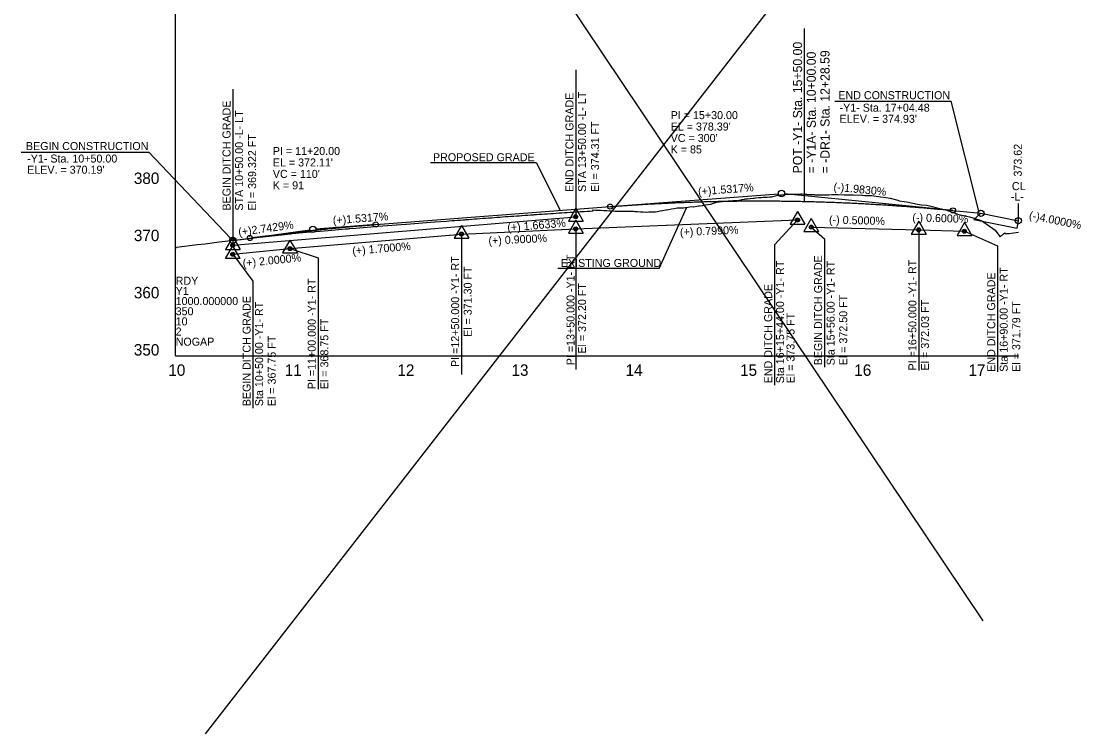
# Model space of a CAD drawing. Extents: x 1625686 to 1640492, y 1161393 to 1175642.
# Drawn here: x 1635777 to 1636704, y 1173205 to 1173828 of the extents above; entities that cross this region are included whole.
import ezdxf

# ---------------------------------------------------------------- set-up
doc = ezdxf.new("R2010")
doc.units = 0
for name, color, linetype in [('Exist Profile Cell', 7, 'Continuous'), ('Exist Vertical Profile Ground Line', 7, 'Continuous'), ('Exist Vertical Profile Horizontal Axis Label Major', 7, 'Continuous'), ('Exist Vertical Profile Vertical Axis Label', 7, 'Continuous'), ('Prop PFL Text', 7, 'Continuous'), ('Prop Vertical Profile Curve Label', 7, 'Continuous'), ('Prop Vertical Profile Ditch Grade Left', 7, 'Continuous'), ('Prop Vertical Profile Ditch Grade Left Label', 7, 'Continuous'), ('Prop Vertical Profile Ditch Grade Right', 7, 'Continuous'), ('Prop Vertical Profile Ditch Grade Right Label', 7, 'Continuous'), ('Prop Vertical Profile Grade', 7, 'Continuous'), ('Prop Vertical Profile Grade Label', 7, 'Continuous'), ('Prop VPI Ditch Grade Left Label', 7, 'Continuous'), ('Prop VPI Ditch Grade Right Label', 7, 'Continuous'), ('Prop VPI Label', 7, 'Continuous'), ('Scratch_Level_3', 7, 'Continuous')]:
    doc.layers.add(name, color=color, linetype=linetype)

msp = doc.modelspace()

# ---------------------------------------------------------------- linework, layer by layer
at = {"layer": 'Exist Profile Cell'}
for q in [(1635911.78, 1174035.94), (1636649.02, 1173535.94), (1635911.78, 1173535.94)]:
    msp.add_line((1635911.78, 1173535.94), q, dxfattribs=at)
at = {"layer": 'Exist Vertical Profile Ground Line'}
msp.add_lwpolyline([(1635911.78, 1173629.69), (1635912.5, 1173630.93), (1635930.84, 1173633.15), (1635937.5, 1173633.96), (1635949.9, 1173635.46), (1635962.76, 1173637.02), (1635968.96, 1173637.73), (1635987.54, 1173639.86), (1635988.02, 1173639.92), (1636007.08, 1173642.1), (1636012.54, 1173642.73), (1636013.03, 1173642.78), (1636013.62, 1173642.83), (1636026.15, 1173643.91), (1636038.32, 1173644.96), (1636045.21, 1173645.56), (1636060.28, 1173646.86), (1636063.04, 1173647.1), (1636063.8, 1173647.16), (1636069.51, 1173647.62), (1636088.9, 1173649.18), (1636113.26, 1173651.14), (1636113.61, 1173651.16), (1636138.26, 1173653), (1636138.61, 1173653.02), (1636148.59, 1173653.76), (1636151.05, 1173653.94), (1636153.51, 1173654.12), (1636155.97, 1173654.3), (1636158.43, 1173654.48), (1636160.89, 1173654.65), (1636163.35, 1173654.82), (1636165.18, 1173654.95), (1636166.05, 1173655.02), (1636168.28, 1173655.2), (1636170.74, 1173655.4), (1636173.2, 1173655.59), (1636175.66, 1173655.78), (1636178.12, 1173655.97), (1636180.58, 1173656.16), (1636183.04, 1173656.34), (1636185.5, 1173656.53), (1636187.96, 1173656.71), (1636190.43, 1173656.89), (1636192.89, 1173657.08), (1636194.17, 1173657.18), (1636195.35, 1173657.26), (1636197.81, 1173657.44), (1636200.27, 1173657.61), (1636202.73, 1173657.78), (1636205.19, 1173657.95), (1636207.65, 1173658.12), (1636210.11, 1173658.29), (1636212.58, 1173658.45), (1636214.37, 1173658.57), (1636215.04, 1173658.62), (1636217.5, 1173658.8), (1636219.96, 1173658.98), (1636222.42, 1173659.16), (1636224.88, 1173659.34), (1636225.29, 1173659.37), (1636227.34, 1173659.51), (1636229.8, 1173659.68), (1636232.26, 1173659.84), (1636234.73, 1173660), (1636237.19, 1173660.17), (1636239.65, 1173660.33), (1636242.11, 1173660.49), (1636244.57, 1173660.66), (1636247.03, 1173660.82), (1636249.49, 1173660.98), (1636251.95, 1173661.14), (1636254.41, 1173661.3), (1636256.87, 1173661.46), (1636259.34, 1173661.61), (1636261.8, 1173661.76), (1636263.1, 1173661.84), (1636264.26, 1173661.91), (1636264.59, 1173661.93), (1636265.63, 1173662.01), (1636266.85, 1173662.09), (1636269.18, 1173662.24), (1636271.64, 1173662.4), (1636274.1, 1173662.55), (1636276.69, 1173662.65), (1636277.27, 1173663.44), (1636279.02, 1173663.36), (1636281.49, 1173663.26), (1636283.95, 1173663.15), (1636286.41, 1173663.04), (1636287.83, 1173662.97), (1636288.87, 1173662.89), (1636291.33, 1173662.68), (1636292.48, 1173662.59), (1636293.79, 1173662.57), (1636296.25, 1173662.55), (1636298.71, 1173662.51), (1636300.71, 1173662.48), (1636301.17, 1173662.47), (1636303.64, 1173662.39), (1636304.59, 1173662.36), (1636306.1, 1173662.35), (1636308.56, 1173662.34), (1636311.02, 1173662.31), (1636312.45, 1173662.3), (1636313.48, 1173662.24), (1636315.94, 1173662.11), (1636318.4, 1173661.97), (1636320.86, 1173661.82), (1636323.32, 1173661.67), (1636323.63, 1173661.65), (1636325.79, 1173661.73), (1636328.25, 1173661.81), (1636330.71, 1173661.9), (1636331.67, 1173661.93), (1636333.17, 1173662.21), (1636335.63, 1173662.67), (1636338.09, 1173663.12), (1636340.55, 1173663.58), (1636341.16, 1173663.69), (1636343.01, 1173664), (1636345.47, 1173664.42), (1636347.94, 1173664.83), (1636350.4, 1173665.24), (1636350.96, 1173665.33), (1636352.86, 1173665.36), (1636355.32, 1173665.39), (1636356.08, 1173665.4), (1636357.78, 1173665.66), (1636360.24, 1173666.03), (1636362.7, 1173666.36), (1636364.66, 1173666.21), (1636365.16, 1173666.29), (1636367.62, 1173666.7), (1636369.2, 1173666.96), (1636370.08, 1173667.09), (1636372.55, 1173667.45), (1636373.56, 1173667.61), (1636375.01, 1173667.82), (1636377.47, 1173668.17), (1636379.93, 1173668.57), (1636382.39, 1173669.38), (1636384.85, 1173670.15), (1636387.31, 1173670.62), (1636389.77, 1173670.85), (1636392.23, 1173671.08), (1636393.29, 1173671.18), (1636394.83, 1173671.2), (1636395.51, 1173671.35), (1636397.16, 1173671.48), (1636399.62, 1173671.67), (1636402.08, 1173671.85), (1636402.45, 1173671.88), (1636404.54, 1173672.16), (1636406.38, 1173672.4), (1636407, 1173672.53), (1636409.46, 1173673.02), (1636410.1, 1173673.15), (1636411.92, 1173673.3), (1636414.38, 1173673.5), (1636416.85, 1173673.7), (1636417.18, 1173673.73), (1636417.77, 1173673.75), (1636419.31, 1173673.96), (1636421.77, 1173674.22), (1636424.23, 1173674.49), (1636425.49, 1173674.62), (1636426.69, 1173674.66), (1636427.92, 1173674.71), (1636429.15, 1173674.75), (1636431.61, 1173674.84), (1636433.23, 1173674.9), (1636434.07, 1173675.12), (1636436.53, 1173675.76), (1636438.61, 1173676.31), (1636439, 1173676.37), (1636441.02, 1173676.72), (1636441.46, 1173676.75), (1636443.92, 1173676.94), (1636446.38, 1173677.14), (1636447.69, 1173677.24), (1636448.84, 1173677.26), (1636449.24, 1173677.33), (1636451.3, 1173677.35), (1636453.76, 1173677.38), (1636456.22, 1173677.4), (1636456.69, 1173677.41), (1636458.68, 1173677.43), (1636459.82, 1173677.45), (1636461.15, 1173677.36), (1636463.61, 1173677.19), (1636464.59, 1173677.12), (1636466.07, 1173677.05), (1636468.53, 1173676.93), (1636470.35, 1173676.84), (1636470.99, 1173676.81), (1636472.53, 1173676.73), (1636473.45, 1173676.72), (1636475.91, 1173676.7), (1636478.37, 1173676.67), (1636479.5, 1173676.66), (1636480.52, 1173676.64), (1636480.83, 1173676.64), (1636483.29, 1173676.78), (1636485.76, 1173676.92), (1636488.54, 1173677.08), (1636491.27, 1173677.12), (1636496.58, 1173676.71), (1636501.71, 1173676.81), (1636504.61, 1173676.76), (1636512.15, 1173676.28), (1636512.65, 1173676.27), (1636514.3, 1173676.25), (1636520.68, 1173676.06), (1636522.59, 1173675.88), (1636528.72, 1173674.93), (1636533.03, 1173674.28), (1636536.75, 1173673.7), (1636543.47, 1173671.95), (1636544.79, 1173671.57), (1636549.19, 1173670.89), (1636552.82, 1173670.37), (1636553.91, 1173670.13), (1636560.86, 1173668.51), (1636564.35, 1173668.08), (1636568.89, 1173667.53), (1636574.79, 1173666.28), (1636576.93, 1173665.71), (1636584.08, 1173663.87), (1636585.23, 1173663.58), (1636593, 1173660.86), (1636595.67, 1173659.74), (1636601.03, 1173658.51), (1636606.1, 1173657.34), (1636609.07, 1173656.45), (1636616.54, 1173654.2), (1636617.1, 1173653.98), (1636618.84, 1173652.69), (1636626.65, 1173647.2), (1636628.59, 1173645.83), (1636629.19, 1173644.96), (1636633.08, 1173639.94), (1636635.96, 1173642.62), (1636637.23, 1173643.51), (1636638.21, 1173642.63), (1636639.18, 1173642.77), (1636640.7, 1173643.03), (1636644.94, 1173643.48), (1636649.02, 1173643.97)], dxfattribs=at)
at = {"layer": 'Prop PFL Text'}
msp.add_line((1636461.78, 1173670.96), (1636461.78, 1173822.24), dxfattribs=at)
at = {"layer": 'Prop Vertical Profile Curve Label'}
for p, q in [((1636616.26, 1173660.59), (1636609.99, 1173655.03)), ((1636649.13, 1173654.01), (1636649.13, 1173669.21)), ((1636609.99, 1173655.03), (1636647.82, 1173647.47)), ((1636647.82, 1173647.47), (1636649.13, 1173654.01))]:
    msp.add_line(p, q, dxfattribs=at)
for centre in [(1636291.78, 1173666.4), (1636591.78, 1173663.02), (1636086.78, 1173650.7), (1635976.78, 1173638.95)]:
    msp.add_circle(centre, 2.25, dxfattribs=at)
at = {"layer": 'Prop Vertical Profile Ditch Grade Left'}
msp.add_line((1635961.78, 1173632.55), (1636261.78, 1173657.5), dxfattribs=at)
at = {"layer": 'Prop Vertical Profile Ditch Grade Right'}
for points in [[(1635961.78, 1173624.69), (1636011.78, 1173629.69), (1636161.78, 1173642.44), (1636261.78, 1173646.94), (1636455.78, 1173654.69)], [(1636467.78, 1173648.44), (1636561.78, 1173646.09), (1636601.78, 1173644.89)]]:
    msp.add_lwpolyline(points, dxfattribs=at)
at = {"layer": 'Prop Vertical Profile Ditch Grade Right Label'}
for p, q in [((1636455.78, 1173662.17), (1636449.33, 1173650.97)), ((1636455.78, 1173662.17), (1636462.28, 1173650.97)), ((1636261.78, 1173654.42), (1636255.33, 1173643.22)), ((1636261.78, 1173654.42), (1636268.28, 1173643.22)), ((1636467.78, 1173655.92), (1636461.33, 1173644.72)), ((1636467.78, 1173655.92), (1636474.28, 1173644.72)), ((1636561.78, 1173653.57), (1636555.33, 1173642.37)), ((1636561.78, 1173653.57), (1636568.28, 1173642.37)), ((1636601.78, 1173652.37), (1636595.33, 1173641.17)), ((1636601.78, 1173652.37), (1636608.28, 1173641.17)), ((1636161.78, 1173649.92), (1636155.33, 1173638.72)), ((1636161.78, 1173649.92), (1636168.28, 1173638.72)), ((1636255.33, 1173643.22), (1636268.28, 1173643.22)), ((1636449.33, 1173650.97), (1636462.28, 1173650.97)), ((1636461.33, 1173644.72), (1636474.28, 1173644.72)), ((1636555.33, 1173642.37), (1636568.28, 1173642.37)), ((1636011.78, 1173637.17), (1636005.33, 1173625.97)), ((1636011.78, 1173637.17), (1636018.28, 1173625.97)), ((1636155.33, 1173638.72), (1636168.28, 1173638.72)), ((1636595.33, 1173641.17), (1636608.28, 1173641.17)), ((1635955.34, 1173620.95), (1635961.8, 1173632.17)), ((1635968.26, 1173620.95), (1635961.8, 1173632.17)), ((1636005.33, 1173625.97), (1636018.28, 1173625.97)), ((1635968.26, 1173620.95), (1635955.34, 1173620.95))]:
    msp.add_line(p, q, dxfattribs=at)
for centre, radius in [((1636455.78, 1173654.69), 1.75), ((1636455.78, 1173654.69), 1.2), ((1636161.78, 1173642.44), 1.75), ((1636161.78, 1173642.44), 1.2), ((1636261.78, 1173646.94), 1.75), ((1636261.78, 1173646.94), 1.2), ((1636467.78, 1173648.44), 1.75), ((1636467.78, 1173648.44), 1.2), ((1636561.78, 1173646.09), 1.75), ((1636561.78, 1173646.09), 1.2), ((1636601.78, 1173644.89), 1.75), ((1636601.78, 1173644.89), 1.2), ((1635961.78, 1173624.69), 1.75), ((1635961.78, 1173624.69), 1.2), ((1636011.78, 1173629.69), 1.75), ((1636011.78, 1173629.69), 1.2)]:
    msp.add_circle(centre, radius, dxfattribs=at)
at = {"layer": 'Prop Vertical Profile Grade'}
for p, q in [((1636086.78, 1173650.7), (1636291.78, 1173666.4)), ((1636591.78, 1173663.02), (1636616.26, 1173660.59)), ((1636616.26, 1173660.59), (1636649.01, 1173654.04)), ((1635961.78, 1173636.89), (1635976.78, 1173638.95))]:
    msp.add_line(p, q, dxfattribs=at)
for points in [[(1636291.78, 1173666.4), (1636297.78, 1173666.85), (1636303.78, 1173667.28), (1636309.78, 1173667.68), (1636315.78, 1173668.07), (1636321.78, 1173668.43), (1636327.78, 1173668.78), (1636333.78, 1173669.1), (1636339.78, 1173669.4), (1636345.78, 1173669.68), (1636351.78, 1173669.94), (1636357.78, 1173670.18), (1636363.78, 1173670.4), (1636369.78, 1173670.59), (1636375.78, 1173670.77), (1636381.78, 1173670.92), (1636387.78, 1173671.05), (1636393.78, 1173671.17), (1636399.78, 1173671.26), (1636405.78, 1173671.32), (1636411.78, 1173671.37), (1636417.78, 1173671.4), (1636423.78, 1173671.41), (1636429.78, 1173671.39), (1636435.78, 1173671.36), (1636441.78, 1173671.3), (1636447.78, 1173671.22), (1636453.78, 1173671.12), (1636459.78, 1173671), (1636465.78, 1173670.86), (1636471.78, 1173670.7), (1636477.78, 1173670.51), (1636483.78, 1173670.31), (1636489.78, 1173670.08), (1636495.78, 1173669.83), (1636501.78, 1173669.57), (1636507.78, 1173669.28), (1636513.78, 1173668.97), (1636519.78, 1173668.64), (1636525.78, 1173668.28), (1636531.78, 1173667.91), (1636537.78, 1173667.52), (1636543.78, 1173667.1), (1636549.78, 1173666.66), (1636555.78, 1173666.21), (1636561.78, 1173665.73), (1636567.78, 1173665.23), (1636573.78, 1173664.71), (1636579.78, 1173664.16), (1636585.78, 1173663.6), (1636591.78, 1173663.02)], [(1635976.78, 1173638.95), (1635978.98, 1173639.25), (1635981.18, 1173639.54), (1635983.38, 1173639.84), (1635985.58, 1173640.13), (1635987.78, 1173640.42), (1635989.98, 1173640.71), (1635992.18, 1173640.99), (1635994.38, 1173641.27), (1635996.58, 1173641.55), (1635998.78, 1173641.83), (1636000.98, 1173642.1), (1636003.18, 1173642.37), (1636005.38, 1173642.64), (1636007.58, 1173642.91), (1636009.78, 1173643.17), (1636011.98, 1173643.43), (1636014.18, 1173643.69), (1636016.38, 1173643.94), (1636018.58, 1173644.2), (1636020.78, 1173644.45), (1636022.98, 1173644.69), (1636025.18, 1173644.94), (1636027.38, 1173645.18), (1636029.58, 1173645.42), (1636031.78, 1173645.66), (1636033.98, 1173645.89), (1636036.18, 1173646.12), (1636038.38, 1173646.35), (1636040.58, 1173646.57), (1636042.78, 1173646.8), (1636044.98, 1173647.02), (1636047.18, 1173647.24), (1636049.38, 1173647.45), (1636051.58, 1173647.66), (1636053.78, 1173647.87), (1636055.98, 1173648.08), (1636058.18, 1173648.29), (1636060.38, 1173648.49), (1636062.58, 1173648.69), (1636064.78, 1173648.88), (1636066.98, 1173649.08), (1636069.18, 1173649.27), (1636071.38, 1173649.46), (1636073.58, 1173649.64), (1636075.78, 1173649.82), (1636077.98, 1173650.01), (1636080.18, 1173650.18), (1636082.38, 1173650.36), (1636084.58, 1173650.53), (1636086.78, 1173650.7)]]:
    msp.add_spline(points, degree=3, dxfattribs=at)
at = {"layer": 'Prop VPI Ditch Grade Left Label'}
for p, q in [((1636261.78, 1173785.99), (1636261.78, 1173657.5)), ((1635961.78, 1173769.15), (1635961.78, 1173632.55)), ((1636261.78, 1173664.98), (1636255.33, 1173653.78)), ((1636261.78, 1173664.98), (1636268.28, 1173653.78)), ((1636255.33, 1173653.78), (1636268.28, 1173653.78)), ((1635961.78, 1173640.03), (1635955.33, 1173628.83)), ((1635961.78, 1173640.03), (1635968.28, 1173628.83)), ((1635955.33, 1173628.83), (1635968.28, 1173628.83))]:
    msp.add_line(p, q, dxfattribs=at)
for centre, radius in [((1636261.78, 1173657.5), 1.75), ((1636261.78, 1173657.5), 1.2), ((1636261.78, 1173657.5), 0.5), ((1635961.78, 1173632.55), 1.75), ((1635961.78, 1173632.55), 1.2)]:
    msp.add_circle(centre, radius, dxfattribs=at)
at = {"layer": 'Prop VPI Ditch Grade Right Label'}
for p, q in [((1636161.78, 1173642.44), (1636161.78, 1173519.52)), ((1636261.78, 1173646.94), (1636261.78, 1173524.02)), ((1636561.78, 1173646.09), (1636561.78, 1173523.17))]:
    msp.add_line(p, q, dxfattribs=at)
for points in [[(1636455.78, 1173654.69), (1636435.56, 1173632.91), (1636435.56, 1173510.23)], [(1636467.78, 1173648.44), (1636479.28, 1173638.36), (1636479.28, 1173525.98)], [(1636601.78, 1173644.89), (1636630.73, 1173632.12), (1636630.73, 1173521.97)], [(1635961.78, 1173624.69), (1635979.3, 1173601.13), (1635979.3, 1173490.24)], [(1636011.78, 1173629.69), (1636036.33, 1173621.7), (1636036.33, 1173506.77)]]:
    msp.add_lwpolyline(points, dxfattribs=at)
msp.add_circle((1635961.78, 1173624.69), 0.5, dxfattribs=at)
at = {"layer": 'Prop VPI Label'}
for p, q in [((1636488.38, 1173758.61), (1636590.22, 1173758.61)), ((1636614.32, 1173662.53), (1636590.22, 1173758.61)), ((1635776.65, 1173714.12), (1635888.2, 1173714.12)), ((1635959.74, 1173638.73), (1635888.2, 1173714.12)), ((1636227.38, 1173704.62), (1636134.83, 1173704.62)), ((1636227.38, 1173704.62), (1636248.12, 1173663.06)), ((1636291.78, 1173666.4), (1636439.04, 1173677.68)), ((1636591.78, 1173663.02), (1636444.52, 1173677.62)), ((1636334.82, 1173612.2), (1636359.01, 1173665.84)), ((1635976.78, 1173638.95), (1636029.06, 1173646.11)), ((1636086.78, 1173650.7), (1636034.52, 1173646.7)), ((1636334.82, 1173612.2), (1636246.22, 1173612.2))]:
    msp.add_line(p, q, dxfattribs=at)
for centre in [(1636441.78, 1173677.89), (1636616.26, 1173660.59), (1636649.01, 1173654.04), (1636031.78, 1173646.49), (1635961.78, 1173636.89)]:
    msp.add_circle(centre, 2.75, dxfattribs=at)
at = {"layer": 'Scratch_Level_3'}
for p, q in [((1635937.75, 1173205.5), (1636672.65, 1174149.36)), ((1636080.34, 1174105.46), (1636617.8, 1173304.27))]:
    msp.add_line(p, q, dxfattribs=at)

# ---------------------------------------------------------------- texts
at = {"layer": 'Exist Profile Cell'}
for s, p in [('RDY', (1635911.78, 1173598.06)), ('Y1', (1635911.78, 1173589.18)), ('1000.000000', (1635911.78, 1173580.31)), ('350', (1635911.78, 1173571.43)), ('10', (1635911.78, 1173562.56)), ('2', (1635911.78, 1173553.69)), ('NOGAP', (1635911.78, 1173544.81))]:
    msp.add_text(s, height=7, dxfattribs=at).set_placement(p)
at = {"layer": 'Exist Vertical Profile Horizontal Axis Label Major'}
for s, p in [('10', (1635905.37, 1173518.44)), ('11', (1636007.2, 1173518.44)), ('12', (1636105.75, 1173518.44)), ('13', (1636205.59, 1173518.44)), ('14', (1636305.43, 1173518.44)), ('15', (1636405.52, 1173518.44)), ('16', (1636505.46, 1173518.44)), ('17', (1636605.32, 1173518.44))]:
    msp.add_text(s, height=10, dxfattribs=at).set_placement(p)
at = {"layer": 'Exist Vertical Profile Vertical Axis Label'}
for s, p in [('380', (1635875.21, 1173686.19)), ('370', (1635875.21, 1173636.19)), ('360', (1635875.21, 1173586.19)), ('350', (1635875.21, 1173536.19))]:
    msp.add_text(s, height=10, dxfattribs=at).set_placement(p)
at = {"layer": 'Prop PFL Text'}
for s, p in [('POT -Y1- Sta. 15+50.00', (1636459.8, 1173695.42)), ('= -Y1A- Sta. 10+00.00 ', (1636471.8, 1173695.42)), ('= -DR1- Sta. 12+28.59', (1636483.8, 1173695.42))]:
    msp.add_text(s, height=8, rotation=90, dxfattribs=at).set_placement(p)
at = {"layer": 'Prop Vertical Profile Curve Label'}
for s, p in [("VC = 300'", (1636344.82, 1173722.89)), ('K = 85', (1636344.82, 1173712.89)), ("VC = 110'", (1635996.78, 1173691.49)), ('K = 91', (1635996.78, 1173681.49))]:
    msp.add_text(s, height=7, dxfattribs=at).set_placement(p)
at = {"layer": 'Prop Vertical Profile Ditch Grade Left Label'}
msp.add_text('(+) 1.6633%', height=7, rotation=4.75416, dxfattribs=at).set_placement((1636202.23, 1173644.55))
at = {"layer": 'Prop Vertical Profile Ditch Grade Right Label'}
for s, rotation, p in [('(-) 0.6000%', 358.28164, (1636556.17, 1173653.55)), ('(-) 0.5000%', 358.5679, (1636483.28, 1173651.55)), ('(+) 0.9000%', 2.57657, (1636185.55, 1173633.11)), ('(+) 0.7990%', 2.28766, (1636353.08, 1173640.63)), ('(+) 1.7000%', 4.85846, (1636066.62, 1173624.19)), ('(+) 2.0000%', 5.71059, (1635970.78, 1173613.45))]:
    msp.add_text(s, height=7, rotation=rotation, dxfattribs=at).set_placement(p)
at = {"layer": 'Prop Vertical Profile Grade Label'}
for s, rotation, p in [('(+)1.5317%', 4.37947, (1636369.07, 1173676.15)), ('(-)1.9830%', 354.33753, (1636487.04, 1173680.4)), ('(+)1.5317%', 4.37947, (1636049.51, 1173650.86)), ('(-)4.0000%', 348.69007, (1636657.89, 1173655.68)), ('(+)2.7429%', 7.80899, (1635967.07, 1173640.64))]:
    msp.add_text(s, height=7, rotation=rotation, dxfattribs=at).set_placement(p)
at = {"layer": 'Prop VPI Ditch Grade Left Label'}
for s, p in [('END DITCH GRADE', (1636259.78, 1173679.19)), ('STA 13+50.00 -L- LT', (1636270.78, 1173679.19)), ('BEGIN DITCH GRADE', (1635959.78, 1173662.9)), ('STA 10+50.00 -L- LT', (1635970.78, 1173662.9)), ('El = 374.31 FT', (1636282.16, 1173679.19)), ('El = 369.322 FT', (1635982.16, 1173662.9))]:
    msp.add_text(s, height=7, rotation=90, dxfattribs=at).set_placement(p)
at = {"layer": 'Prop VPI Ditch Grade Right Label'}
for s, p in [('PI =13+50.000 -Y1- RT ', (1636260.7, 1173527.69)), ('PI =12+50.000 -Y1- RT', (1636159.78, 1173526.15)), ('Sta 16+15+44.00 -Y1- RT', (1636444.04, 1173511.9)), ('BEGIN DITCH GRADE', (1636477.34, 1173527.64)), ('Sta 15+56.00 -Y1- RT', (1636488.28, 1173527.64)), ('PI =16+50.000 -Y1- RT', (1636559.78, 1173523.17)), ('El = 371.30 FT', (1636170.78, 1173552.44)), ('END DITCH GRADE', (1636628.72, 1173521.97)), ('Sta 16+90.00 -Y1- RT', (1636639.66, 1173521.97)), ('PI =11+00.000 -Y1- RT', (1636034.33, 1173506.77)), ('El = 372.20 FT', (1636270.78, 1173537.84)), ('END DITCH GRADE', (1636433.62, 1173511.9)), ('BEGIN DITCH GRADE', (1635977.36, 1173491.9)), ('El = 372.50 FT', (1636499.28, 1173527.64)), ('Sta 10+50.00 -Y1- RT', (1635988.3, 1173491.9)), ('El = 372.03 FT', (1636570.78, 1173523.17)), ('El = 371.79 FT', (1636650.66, 1173521.97)), ('El = 368.75 FT', (1636045.33, 1173506.77)), ('El = 373.75 FT', (1636453.16, 1173511.9)), ('El = 367.75 FT', (1635999.3, 1173491.9))]:
    msp.add_text(s, height=7, rotation=90, dxfattribs=at).set_placement(p)
at = {"layer": 'Prop VPI Label'}
for s, p in [('END CONSTRUCTION', (1636491.5, 1173760.33)), ('-Y1- Sta. 17+04.48', (1636492.57, 1173749.39)), ('PI = 15+30.00', (1636344.82, 1173742.89)), ("ELEV. = 374.93'", (1636492.57, 1173739.64)), ("EL = 378.39'", (1636344.82, 1173732.89)), ('BEGIN CONSTRUCTION', (1635780.8, 1173715.84)), ('PI = 11+20.00', (1635996.78, 1173711.49)), ('-Y1- Sta. 10+50.00', (1635781.88, 1173704.9)), ("EL = 372.11'", (1635996.78, 1173701.49)), ('PROPOSED GRADE', (1636136.88, 1173706.06)), ("ELEV. = 370.19'", (1635781.88, 1173695.15)), ('CL', (1636643.33, 1173680.81)), ('-L-', (1636642.36, 1173671.63)), ('EXISTING GROUND', (1636248.74, 1173613.64))]:
    msp.add_text(s, height=7, dxfattribs=at).set_placement(p)
msp.add_text('373.62', height=7, rotation=90, dxfattribs=at).set_placement((1636651.97, 1173692.65))

doc.saveas('drawing.dxf')
